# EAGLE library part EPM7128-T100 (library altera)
EPM70128 MAX 7000 family
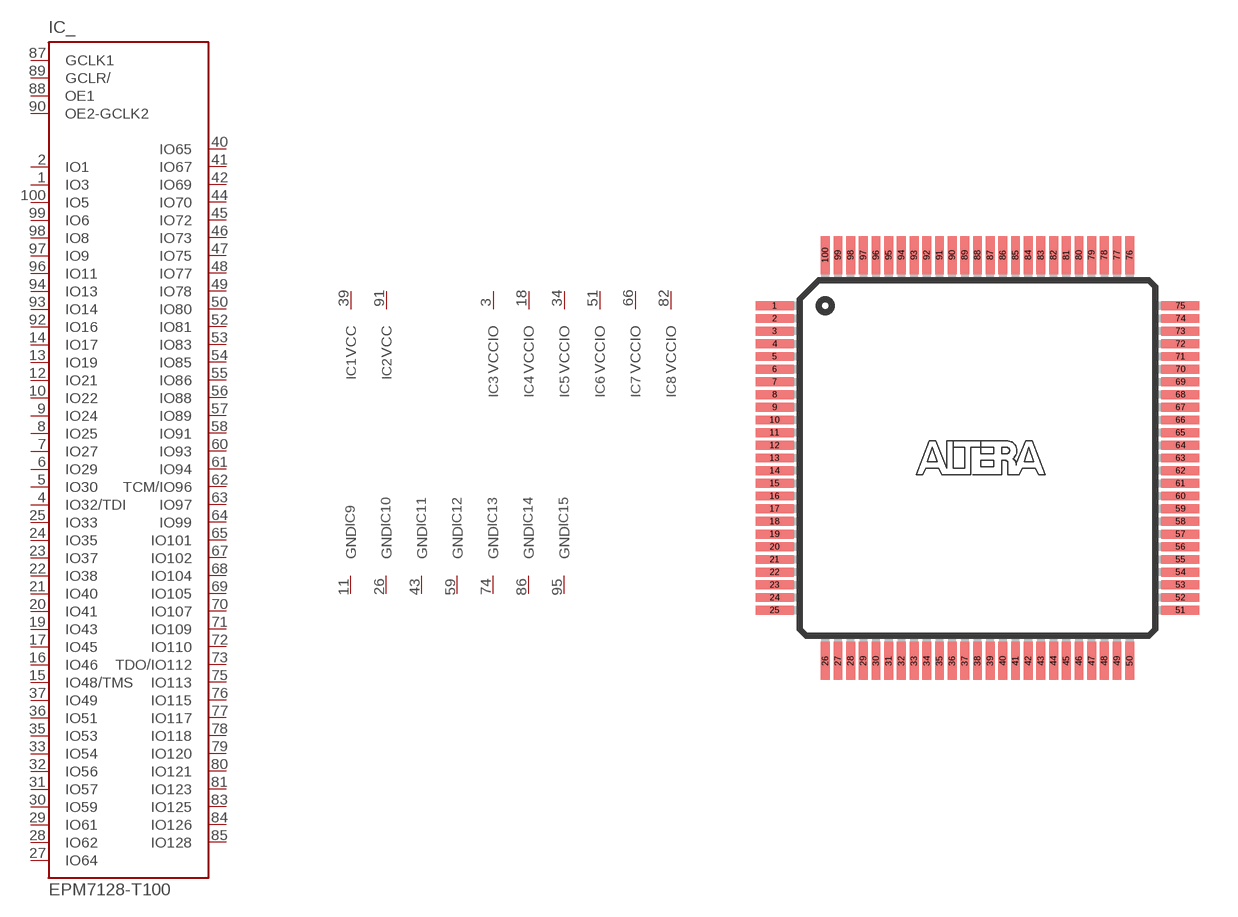
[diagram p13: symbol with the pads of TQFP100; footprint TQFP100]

Designator prefix IC; gates _=7128P100 1=VCC 2=VCC 3=VCCIO 4=VCCIO 5=VCCIO 6=VCCIO 7=VCCIO 8=VCCIO 9=GND 10=GND 11=GND 12=GND 13=GND 14=GND 15=GND 16=GND

## EPM7128-T100  [TQFP100]
1  _:IO3
2  _:IO1
3  3:VCCIO  pwr
4  _:IO32/TDI
5  _:IO30
6  _:IO29
7  _:IO27
8  _:IO25
9  _:IO24
10  _:IO22
11  9:GND  pwr
12  _:IO21
13  _:IO19
14  _:IO17
15  _:IO48/TMS
16  _:IO46
17  _:IO45
18  4:VCCIO  pwr
19  _:IO43
20  _:IO41
21  _:IO40
22  _:IO38
23  _:IO37
24  _:IO35
25  _:IO33
26  10:GND  pwr
27  _:IO64
28  _:IO62
29  _:IO61
30  _:IO59
31  _:IO57
32  _:IO56
33  _:IO54
34  5:VCCIO  pwr
35  _:IO53
36  _:IO51
37  _:IO49
38  16:GND  pwr
39  1:VCC  pwr
40  _:IO65
41  _:IO67
42  _:IO69
43  11:GND  pwr
44  _:IO70
45  _:IO72
46  _:IO73
47  _:IO75
48  _:IO77
49  _:IO78
50  _:IO80
51  6:VCCIO  pwr
52  _:IO81
53  _:IO83
54  _:IO85
55  _:IO86
56  _:IO88
57  _:IO89
58  _:IO91
59  12:GND  pwr
60  _:IO93
61  _:IO94
62  _:TCM/IO96
63  _:IO97
64  _:IO99
65  _:IO101
66  7:VCCIO  pwr
67  _:IO102
68  _:IO104
69  _:IO105
70  _:IO107
71  _:IO109
72  _:IO110
73  _:TDO/IO112
74  13:GND  pwr
75  _:IO113
76  _:IO115
77  _:IO117
78  _:IO118
79  _:IO120
80  _:IO121
81  _:IO123
82  8:VCCIO  pwr
83  _:IO125
84  _:IO126
85  _:IO128
86  14:GND  pwr
87  _:GCLK1  in
88  _:OE1  in
89  _:GCLR/  in
90  _:OE2-GCLK2  in
91  2:VCC  pwr
92  _:IO16
93  _:IO14
94  _:IO13
95  15:GND  pwr
96  _:IO11
97  _:IO9
98  _:IO8
99  _:IO6
100  _:IO5

## Footprint TQFP100 (pad centres in mm)
Plastic Thin Quad Flat Pack
smd 1.5 x 0.35: 1 -8,6; 2 -8,5.5; 3 -8,5; 4 -8,4.5; 5 -8,4; 6 -8,3.5; 7 -8,3; 8 -8,2.5; 9 -8,2; 10 -8,1.5; 11 -8,1; 12 -8,0.5; 13 -8,0; 14 -8,-0.5; 15 -8,-1; 16 -8,-1.5; 17 -8,-2; 18 -8,-2.5; 19 -8,-3; 20 -8,-3.5; 21 -8,-4; 22 -8,-4.5; 23 -8,-5; 24 -8,-5.5; 25 -8,-6; 51 8,-6; 52 8,-5.5; 53 8,-5; 54 8,-4.5; 55 8,-4; 56 8,-3.5; 57 8,-3; 58 8,-2.5; 59 8,-2; 60 8,-1.5; 61 8,-1; 62 8,-0.5; 63 8,0; 64 8,0.5; 65 8,1; 66 8,1.5; 67 8,2; 68 8,2.5; 69 8,3; 70 8,3.5; 71 8,4; 72 8,4.5; 73 8,5; 74 8,5.5; 75 8,6
smd 0.35 x 1.5: 26 -6,-8; 27 -5.5,-8; 28 -5,-8; 29 -4.5,-8; 30 -4,-8; 31 -3.5,-8; 32 -3,-8; 33 -2.5,-8; 34 -2,-8; 35 -1.5,-8; 36 -1,-8; 37 -0.5,-8; 38 0,-8; 39 0.5,-8; 40 1,-8; 41 1.5,-8; 42 2,-8; 43 2.5,-8; 44 3,-8; 45 3.5,-8; 46 4,-8; 47 4.5,-8; 48 5,-8; 49 5.5,-8; 50 6,-8; 76 6,8; 77 5.5,8; 78 5,8; 79 4.5,8; 80 4,8; 81 3.5,8; 82 3,8; 83 2.5,8; 84 2,8; 85 1.5,8; 86 1,8; 87 0.5,8; 88 0,8; 89 -0.5,8; 90 -1,8; 91 -1.5,8; 92 -2,8; 93 -2.5,8; 94 -3,8; 95 -3.5,8; 96 -4,8; 97 -4.5,8; 98 -5,8; 99 -5.5,8; 100 -6,8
